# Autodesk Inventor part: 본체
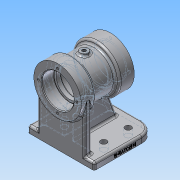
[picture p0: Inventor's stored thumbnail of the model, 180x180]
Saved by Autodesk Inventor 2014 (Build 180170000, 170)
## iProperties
Created: 2020-06
Part Number: 본체
Material: 알루미늄 6061
Document SubType Name: Modeling
Designer: net
Density: 2.71 g/cm^3
Appearance: 알루미늄 - 평지
Mass: 728.075 g
Surface Area: 641.49 cm^2
Volume: 268.662 cm^3
Author: net
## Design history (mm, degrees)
sketch "스케치1"
  geometry: L1 (39, 0)-(-39, 0); L2 (39, 0)-(39, 35); L3 (39, 35)-(17, 35); L4 (17, 35)-(17, 29); L5 (17, 29)-(-17, 29); L6 (-17, 29)-(-17, 35); L7 (-17, 35)-(-39, 35); L8 (-39, 35)-(-39, 0); 2 further points
  constraints: 16 end point, 4 parallel, 2 collinear, 2 perpendicular, 1 coincident, 1 horizontal, 1 midpoint
  dimensions: "d0" = 78 distance of L1.start L1.end; "d1" = 22 distance of L2.end L3.end; "d2" = 22 distance of L6.end L7.end; "d3" = 70 diameter of L3 L1; "d4" = 58 diameter of L5 L1
revolve "회전1" sketch "스케치1" stored, may be unused: angle "d5" = 90 deg
sketch "스케치2"
  geometry: C1 r 35 at (0, 0) reference; C2 r 23.5 at (0, 0)
  constraints: 1 centre point, 1 coincident
  dimensions: "d6" = 47 diameter of C2
extrude "돌출1" cut sketch "스케치2" distance "d7" = 18; taper "d8" = 0 deg
sketch "스케치3"
  geometry: C1 r 23 at (0, 0); 1 further point
  constraints: 1 centre point, 1 coincident
  dimensions: "d9" = 46 diameter of C1
extrude "돌출2" cut sketch "스케치3" stored distance "d10" = 30; taper "d11" = 0 deg
fillet "모깎기1" dims "d12" = 0.3
fillet "모깎기2" dims "d13" = 3
sketch "스케치4"
  geometry: C1 r 23.2 at (0, 0) reference; C2 r 20 at (0, 0)
  constraints: 1 centre point, 1 coincident
  dimensions: "d14" = 40 diameter of C2
extrude "돌출3" cut sketch "스케치4" stored distance "d15" = 30; taper "d16" = 0 deg
chamfer "모따기1" distance "d17" = 1; stored, may be unused: second distance "d18" = 2, angle "d19" = 45 deg
sketch "스케치5" dims "d20" = 57
  geometry: C1 r 35 at (0, 0) reference; C2 r 24.5 at (0, 0) reference; 2 further points
  constraints: 2 vertical alignment, 1 coincident, 2 other
hole "구멍1" sketch "스케치5" at (0, 28.5) diameter "d21" = 3.242; stored, may be unused: countersink angle "d25" = 90 deg, drill point angle "d27" = 118 deg; dims "d22" = 10, "d23" = 4, "d24" = 2, "d26" = 12
node "작업 평면2"
sketch "스케치7"
  geometry: C1 r 6 at (0, 0); 1 further point
  constraints: 1 centre point, 1 coincident
  dimensions: "d34" = 12 diameter of C1
extrude "돌출4" join sketch "스케치7" stored distance "d35" = 30; taper "d36" = 0 deg
hole "구멍2" diameter "d39" = 5.188; stored, may be unused: countersink angle "d43" = 90 deg, drill point angle "d45" = 118 deg; dims "d37" = 10, "d38" = 10, "d40" = 10, "d41" = 4, "d42" = 2, "d44" = 12
fillet "모깎기3" dims "d46" = 3
node "작업 평면4"
sketch "스케치8"
  geometry: L1 (-39, 35)-(-39, -35) reference; L2 (-34, 49)-(56, 49); L3 (56, 49)-(56, -49); L4 (56, -49)-(-34, -49); L5 (-34, -49)-(-34, 49); 3 further points
  constraints: 8 end point, 2 midpoint, 2 parallel, 1 horizontal, 1 horizontal alignment, 1 perpendicular
  dimensions: "d49" = 90 distance of L2.start L2.end; "d50" = 98 distance of L2.end L3.end; "d51" = 5 distance between parallel lines of L5 L1
extrude "돌출5" join sketch "스케치8" distance "d52" = 10; taper "d53" = 0 deg
sketch "스케치9"
  geometry: L1 (-34, 49)-(-34, -49) reference; L2 (-34, 35)-(-24, 35); L3 (-24, 35)-(-24, -35); L4 (-24, -35)-(-34, -35); L5 (-34, -35)-(-34, 35); 3 further points
  constraints: 8 end point, 3 midpoint, 2 parallel, 1 coincident, 1 horizontal, 1 perpendicular
  dimensions: "d54" = 70 distance of L4.end L2.start; "d55" = 10 distance of L2.start L2.end
extrude "돌출6" join sketch "스케치9" stored distance "d56" = 10; taper "d57" = 0 deg
sketch "스케치10"
  geometry: L1 (21, 20)-(15, 20) reference; L2 (12, 23)-(2.594, 23) reference; L3 (2.594, 23)-(2.594, 32) reference; L4 (2.594, 32)-(6, 32) reference; L5 (9, 29)-(14, 29) reference; L6 (20, 35)-(39, 35) reference; L7 (39, 35)-(39, 30.121) reference; L8 (39, 30.121)-(27, 30.121) reference; L9 (27, 30.121)-(26.026, 28.5) reference; L10 (26.026, 28.5)-(27, 26.879) reference; L11 (27, 26.879)-(39, 26.879) reference; L12 (39, 26.879)-(39, 24.5) reference; L13 (39, 24.5)-(38, 23.5) reference; L14 (38, 23.5)-(21.3, 23.5) reference; L15 (21, 23.2)-(21, 20) reference; L16 (-15, 20)-(-21, 20) reference; L17 (-21, 20)-(-21, 23.2) reference; L18 (-21.3, 23.5)-(-38, 23.5) reference; L19 (-38, 23.5)-(-39, 24.5) reference; L20 (-39, 24.5)-(-39, 26.879) reference; L21 (-39, 26.879)-(-27, 26.879) reference; L22 (-27, 26.879)-(-26.026, 28.5) reference; L23 (-26.026, 28.5)-(-27, 30.121) reference; L24 (-27, 30.121)-(-39, 30.121) reference; L25 (-39, 30.121)-(-39, 35) reference; L26 (-39, 35)-(-20, 35) reference; L27 (-14, 29)-(-9, 29) reference; L28 (-6, 32)-(-2.594, 32) reference; L29 (-2.594, 32)-(-2.594, 23) reference; L30 (-2.594, 23)-(-12, 23) reference; L31 (-21, -20)-(-15, -20) reference; L32 (-12, -23)-(12, -23) reference; L33 (15, -20)-(21, -20) reference; L34 (21, -20)-(21, -23.2) reference; L35 (21.3, -23.5)-(38, -23.5) reference; L36 (38, -23.5)-(39, -24.5) reference; L37 (39, -24.5)-(39, -26.879) reference; L38 (39, -26.879)-(27, -26.879) reference; L39 (27, -26.879)-(26.026, -28.5) reference; L40 (26.026, -28.5)-(27, -30.121) reference; L41 (27, -30.121)-(39, -30.121) reference; L42 (39, -30.121)-(39, -35) reference; L43 (39, -35)-(34, -35) reference; L44 (34, -35)-(34, -80) reference; L45 (34, -80)-(-56, -80) reference; L46 (-56, -80)-(-56, -70) reference; L47 (-56, -70)-(24, -70) reference; L48 (24, -70)-(24, -35) reference; L49 (24, -35)-(20, -35) reference; L50 (14, -29)-(-14, -29) reference; L51 (-20, -35)-(-39, -35) reference; L52 (-39, -35)-(-39, -30.121) reference; L53 (-39, -30.121)-(-27, -30.121) reference; L54 (-27, -30.121)-(-26.026, -28.5) reference; L55 (-26.026, -28.5)-(-27, -26.879) reference; L56 (-27, -26.879)-(-39, -26.879) reference; L57 (-39, -26.879)-(-39, -24.5) reference; L58 (-39, -24.5)-(-38, -23.5) reference; L59 (-38, -23.5)-(-21.3, -23.5) reference; L60 (-21, -23.2)-(-21, -20) reference; L61 (-44, -70)-(-31.261, -35); A1 r 3 centre (12, 20) between (15, 20) and (12, 23) reference; A2 r 3 centre (14, 32) between (14, 29) and (17, 32) reference; A3 r 3 centre (20, 32) between (20, 35) and (17, 32) reference; A4 r 0.3 centre (21.3, 23.2) between (21.3, 23.5) and (21, 23.2) reference; A5 r 0.3 centre (-21.3, 23.2) between (-21, 23.2) and (-21.3, 23.5) reference; A6 r 3 centre (-20, 32) between (-17, 32) and (-20, 35) reference; A7 r 3 centre (-14, 32) between (-17, 32) and (-14, 29) reference; A8 r 3 centre (-12, 20) between (-12, 23) and (-15, 20) reference; A9 r 3 centre (-12, -20) between (-15, -20) and (-12, -23) reference; A10 r 3 centre (12, -20) between (12, -23) and (15, -20) reference; A11 r 0.3 centre (21.3, -23.2) between (21, -23.2) and (21.3, -23.5) reference; A12 r 3 centre (20, -32) between (17, -32) and (20, -35) reference; A13 r 3 centre (14, -32) between (17, -32) and (14, -29) reference; A14 r 3 centre (-14, -32) between (-14, -29) and (-17, -32) reference; A15 r 3 centre (-20, -32) between (-20, -35) and (-17, -32) reference; A16 r 0.3 centre (-21.3, -23.2) between (-21.3, -23.5) and (-21, -23.2) reference; 1 further point
  constraints: 2 end point, 2 point on line, 2 other
  dimensions: "d58" = 12 horizontal distance of L45.end L61.start; "d59" = 70 deg angle of L61 L47
feature "리브1" sketch "스케치10" dims "d60" = 1, "d61" = 10, "d62" = 0, "d63" = 0, "d64" = 1, "d65" = 1
fillet "모깎기4" dims "d66" = 20
fillet "모깎기5" dims "d67" = 3
fillet "모깎기6" dims "d68" = 3
fillet "모깎기7" dims "d69" = 3
fillet "모깎기8" dims "d70" = 3
fillet "모깎기9" dims "d71" = 3
fillet "모깎기10" dims "d72" = 3
sketch "스케치11"
  geometry: A1 r 17 centre (36, -29) between (36, -46) and (53, -29) reference; A2 r 17 centre (36, 29) between (53, 29) and (36, 46) reference; 5 further points
  constraints: 2 coincident, 2 horizontal alignment, 1 vertical alignment
  dimensions: "d73" = 36 distance of point (36, 29) point (0, 29); "d74" = 58 distance of point (36, -29) point (36, 29) (derived)
hole "구멍3" sketch "스케치11" at (36, 29), (0, 29), (36, -29), (0, -29) diameter "d75" = 9; stored, may be unused: countersink angle "d79" = 90 deg, drill point angle "d81" = 118 deg; dims "d76" = 10, "d77" = 4, "d78" = 2, "d80" = 12
sketch "스케치12"
  geometry: L1 (67, 0)-(0, 0) reference; L2 (-3, 7)-(-3, 0) reference; 2 further points
  constraints: 1 other
  dimensions: "d82" = 4 distance from line of point (42, 4) L1; "d83" = 45 distance from line of point (42, 4) L2
feature "엠보싱1" sketch "스케치12" dims "d9" = 46, "d84" = 0.5, "d85" = 0
node "솔리드1"
mirror "대칭1"
pattern_circular "원형 패턴1" dims angle "d29" = 360 deg
mirror "대칭2"
node "절단 모서리 투영1"
other parameters: "d33" = 32
